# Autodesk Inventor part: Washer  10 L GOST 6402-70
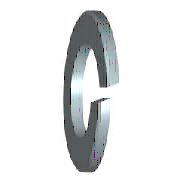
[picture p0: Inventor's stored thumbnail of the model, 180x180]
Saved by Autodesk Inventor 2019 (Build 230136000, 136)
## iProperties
Created: 2018-01
Part Number: Washer  10 L GOST 6402-70
Material: Steel, Mild
Description: Lock washers
Document SubType Name: Modeling
Standard: GOST 6402-70
Designer: m.vorobev
Standards Organization: GOST
Language: en-US
Size Designation: 10 L
Categories: <MemberInstance><Categories><Category DisplayName="Fasteners" InternalName="e4da775c-781d-43d5-af7c-5136215cf5a6" Mnemonic="FSTN"><Category DisplayName="Washers
Density: 7.85 g/cm^3
Appearance: Semi-Polished
IsCustomPart: 0
Author: m.vorobev
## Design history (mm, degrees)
sketch "Sketch1"
  geometry: C1 r 7.6 at (0, 0); C2 r 5.1 at (0, 0); 1 further point
  constraints: 2 centre point, 2 coincident
  dimensions: "d0" = 10.2 diameter of C2 (= SD1); "d1" = 15.2 diameter of C1 (= SD2)
extrude "Body" new body sketch "Sketch1" distance "d2" = 2 (= SD); taper "d3" = 0 deg
sketch "Sketch2"
  geometry: L1 (0, -5.1)-(0, 5.1) reference; L2 (2, 7.6)-(2, -7.6) reference; L3 (-1.2, 0)-(7.2, 0) reference; L4 (0, -0.4)-(2, 0.328); L5 (0, 0.4)-(2, 1.128)
  constraints: 4 end point, 4 point on line, 1 parallel
  dimensions: "d4" = 0.4 distance from line of L3 L4.start (= 0.2 x SD); "d5" = 0.4 distance from line of L3 L5.start (= 0.2 x SD); "d6" = 70 deg angle of L2 L4 (= FAWI)
extrude "Cut" cut sketch "Sketch2" stored distance "d7" = 2 (= SD); taper "d8" = 0 deg
workaxis "Work Axis1"
workplane "Work Plane1"
body "Solid1"
other parameters: "SD1" = 10.2 [user parameter; used in 1 equation term], "SD2" = 15.2 [user parameter; used in 1 equation term], "SD" = 2 [user parameter; used in 4 equation terms], "FAWI" = 70 deg [user parameter; used in 1 equation term], "d9" = 0, "d10" = 0, "d11" = 0, "d12" = 0
